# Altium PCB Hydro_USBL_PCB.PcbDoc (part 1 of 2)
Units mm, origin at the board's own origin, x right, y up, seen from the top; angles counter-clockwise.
Board outline 75 x 75 mm, 4 copper layers (Top Layer, Layer 1, Layer 2, Bottom Layer), stack 0.871 mm thick; 273 components, 152 nets, 824 pads, 165 vias.
Unrouted connection lines stored in the file: 155.
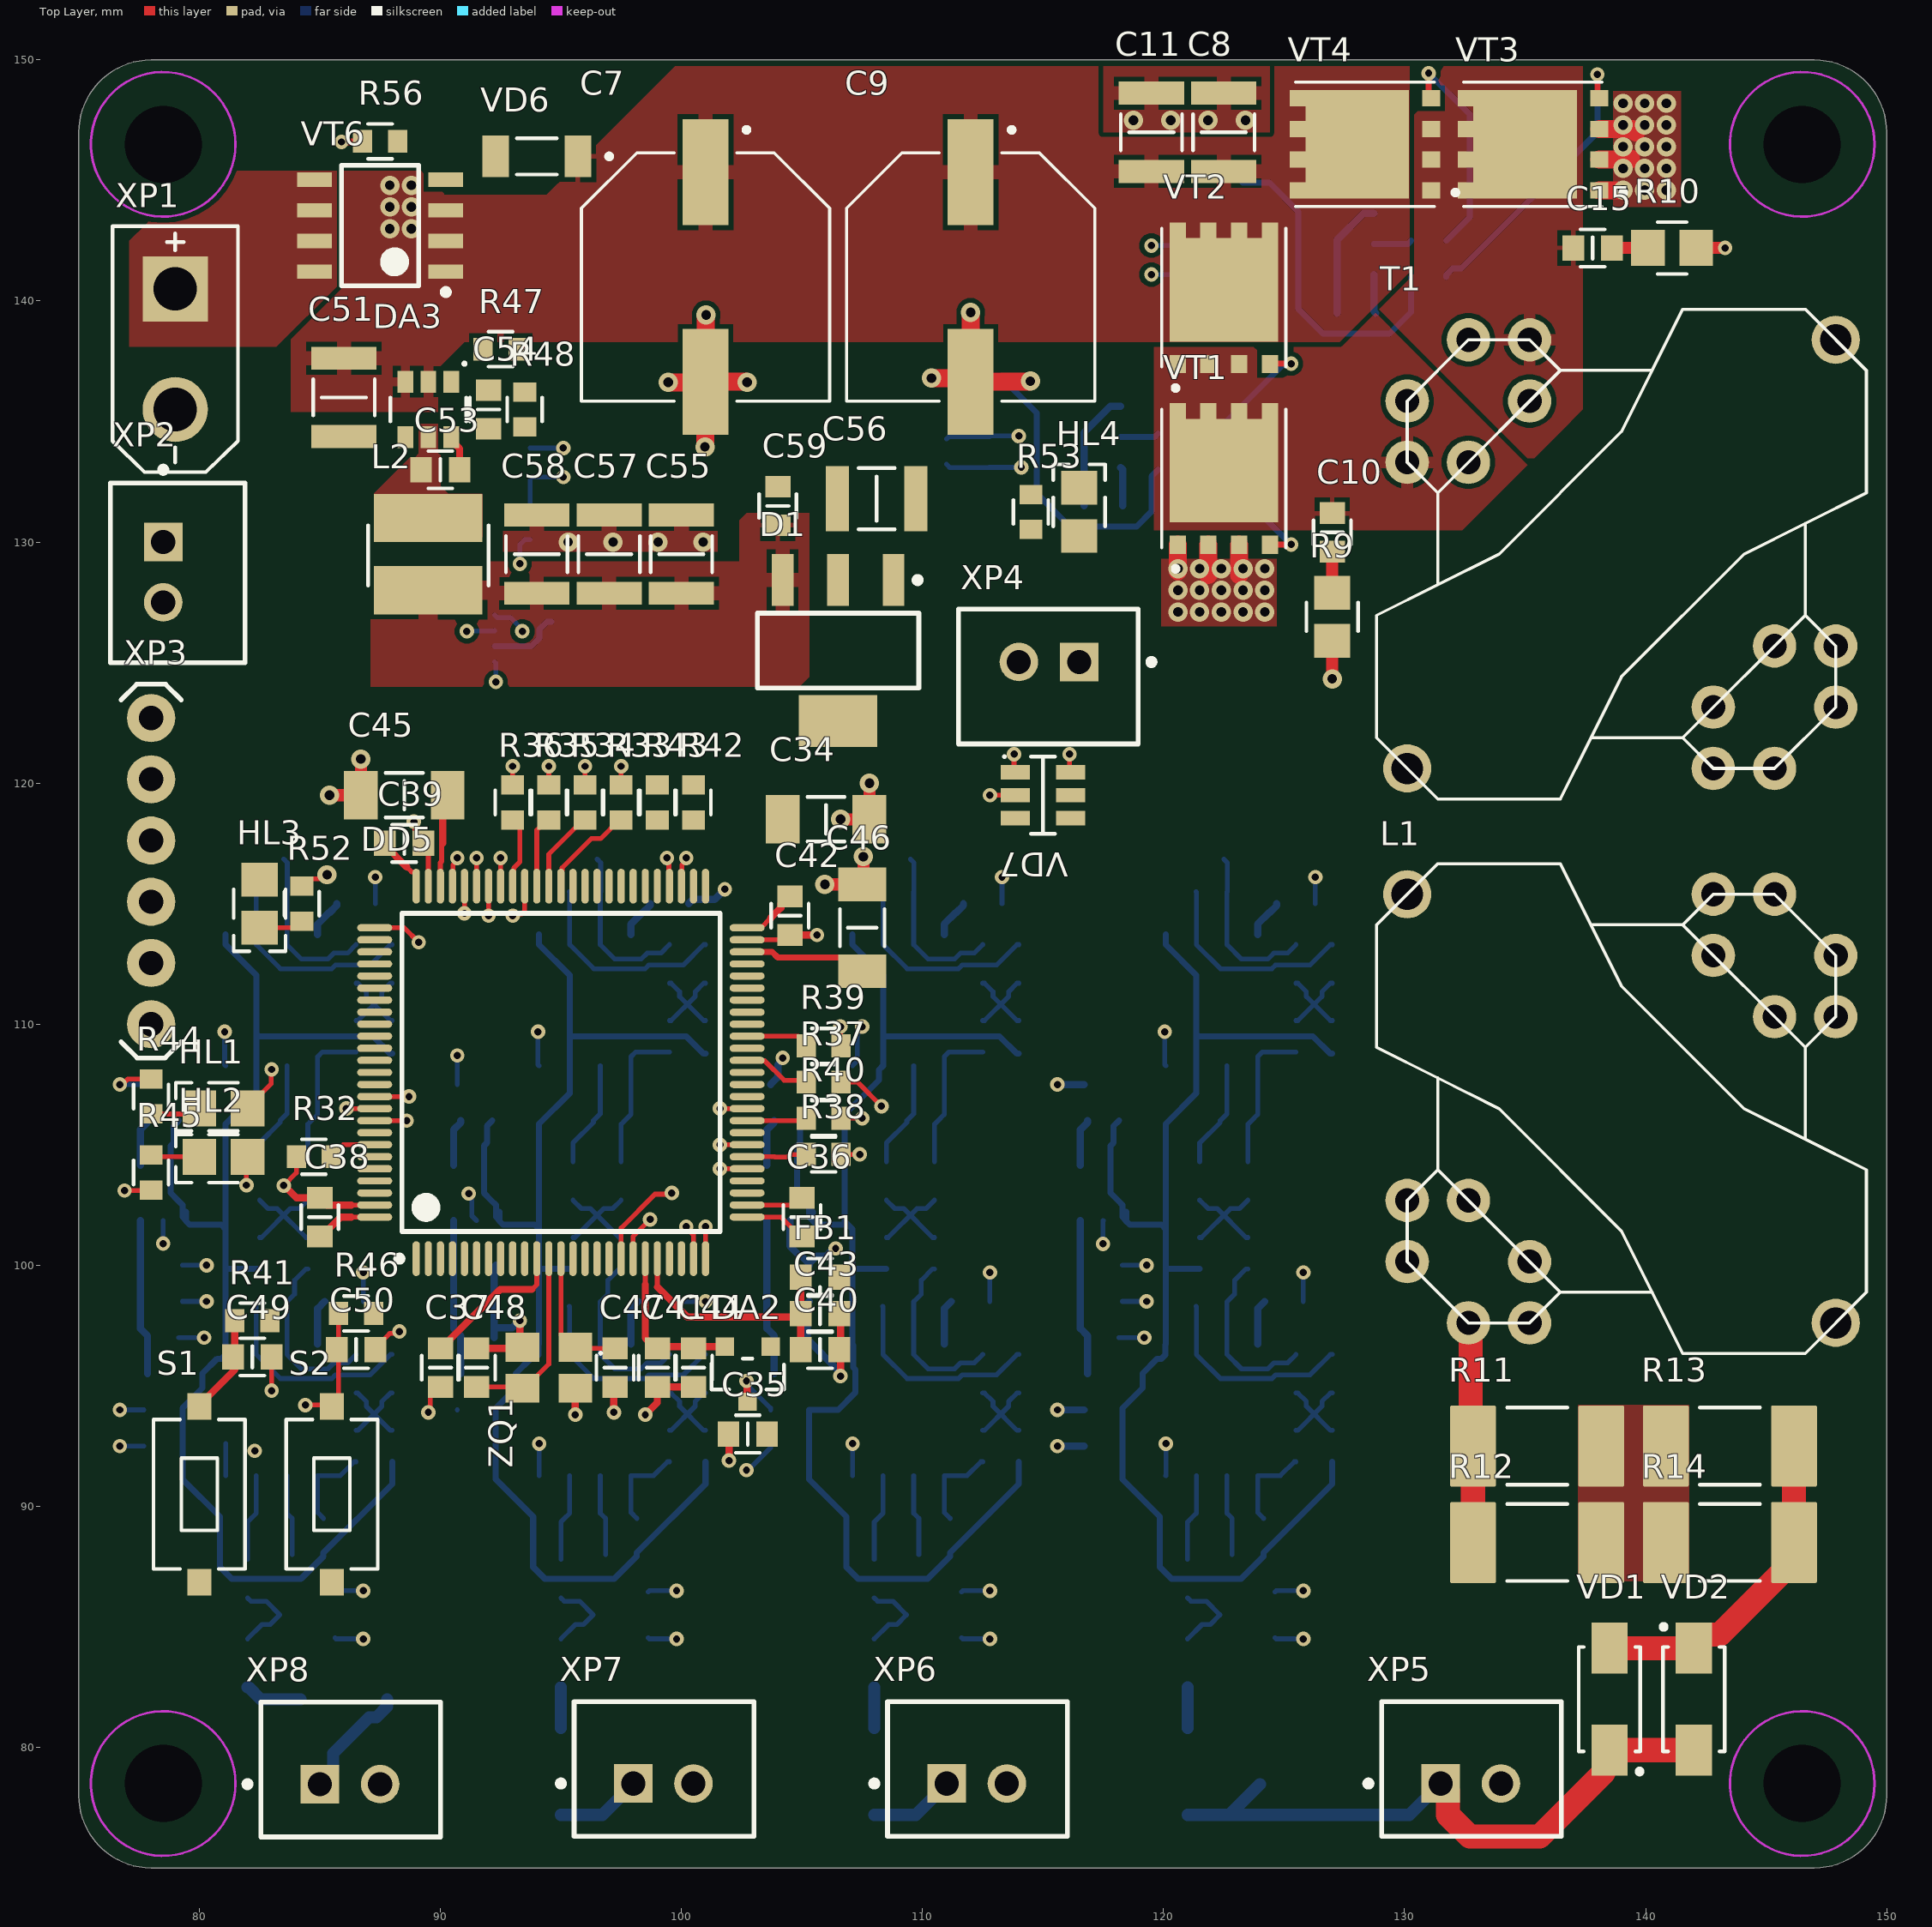
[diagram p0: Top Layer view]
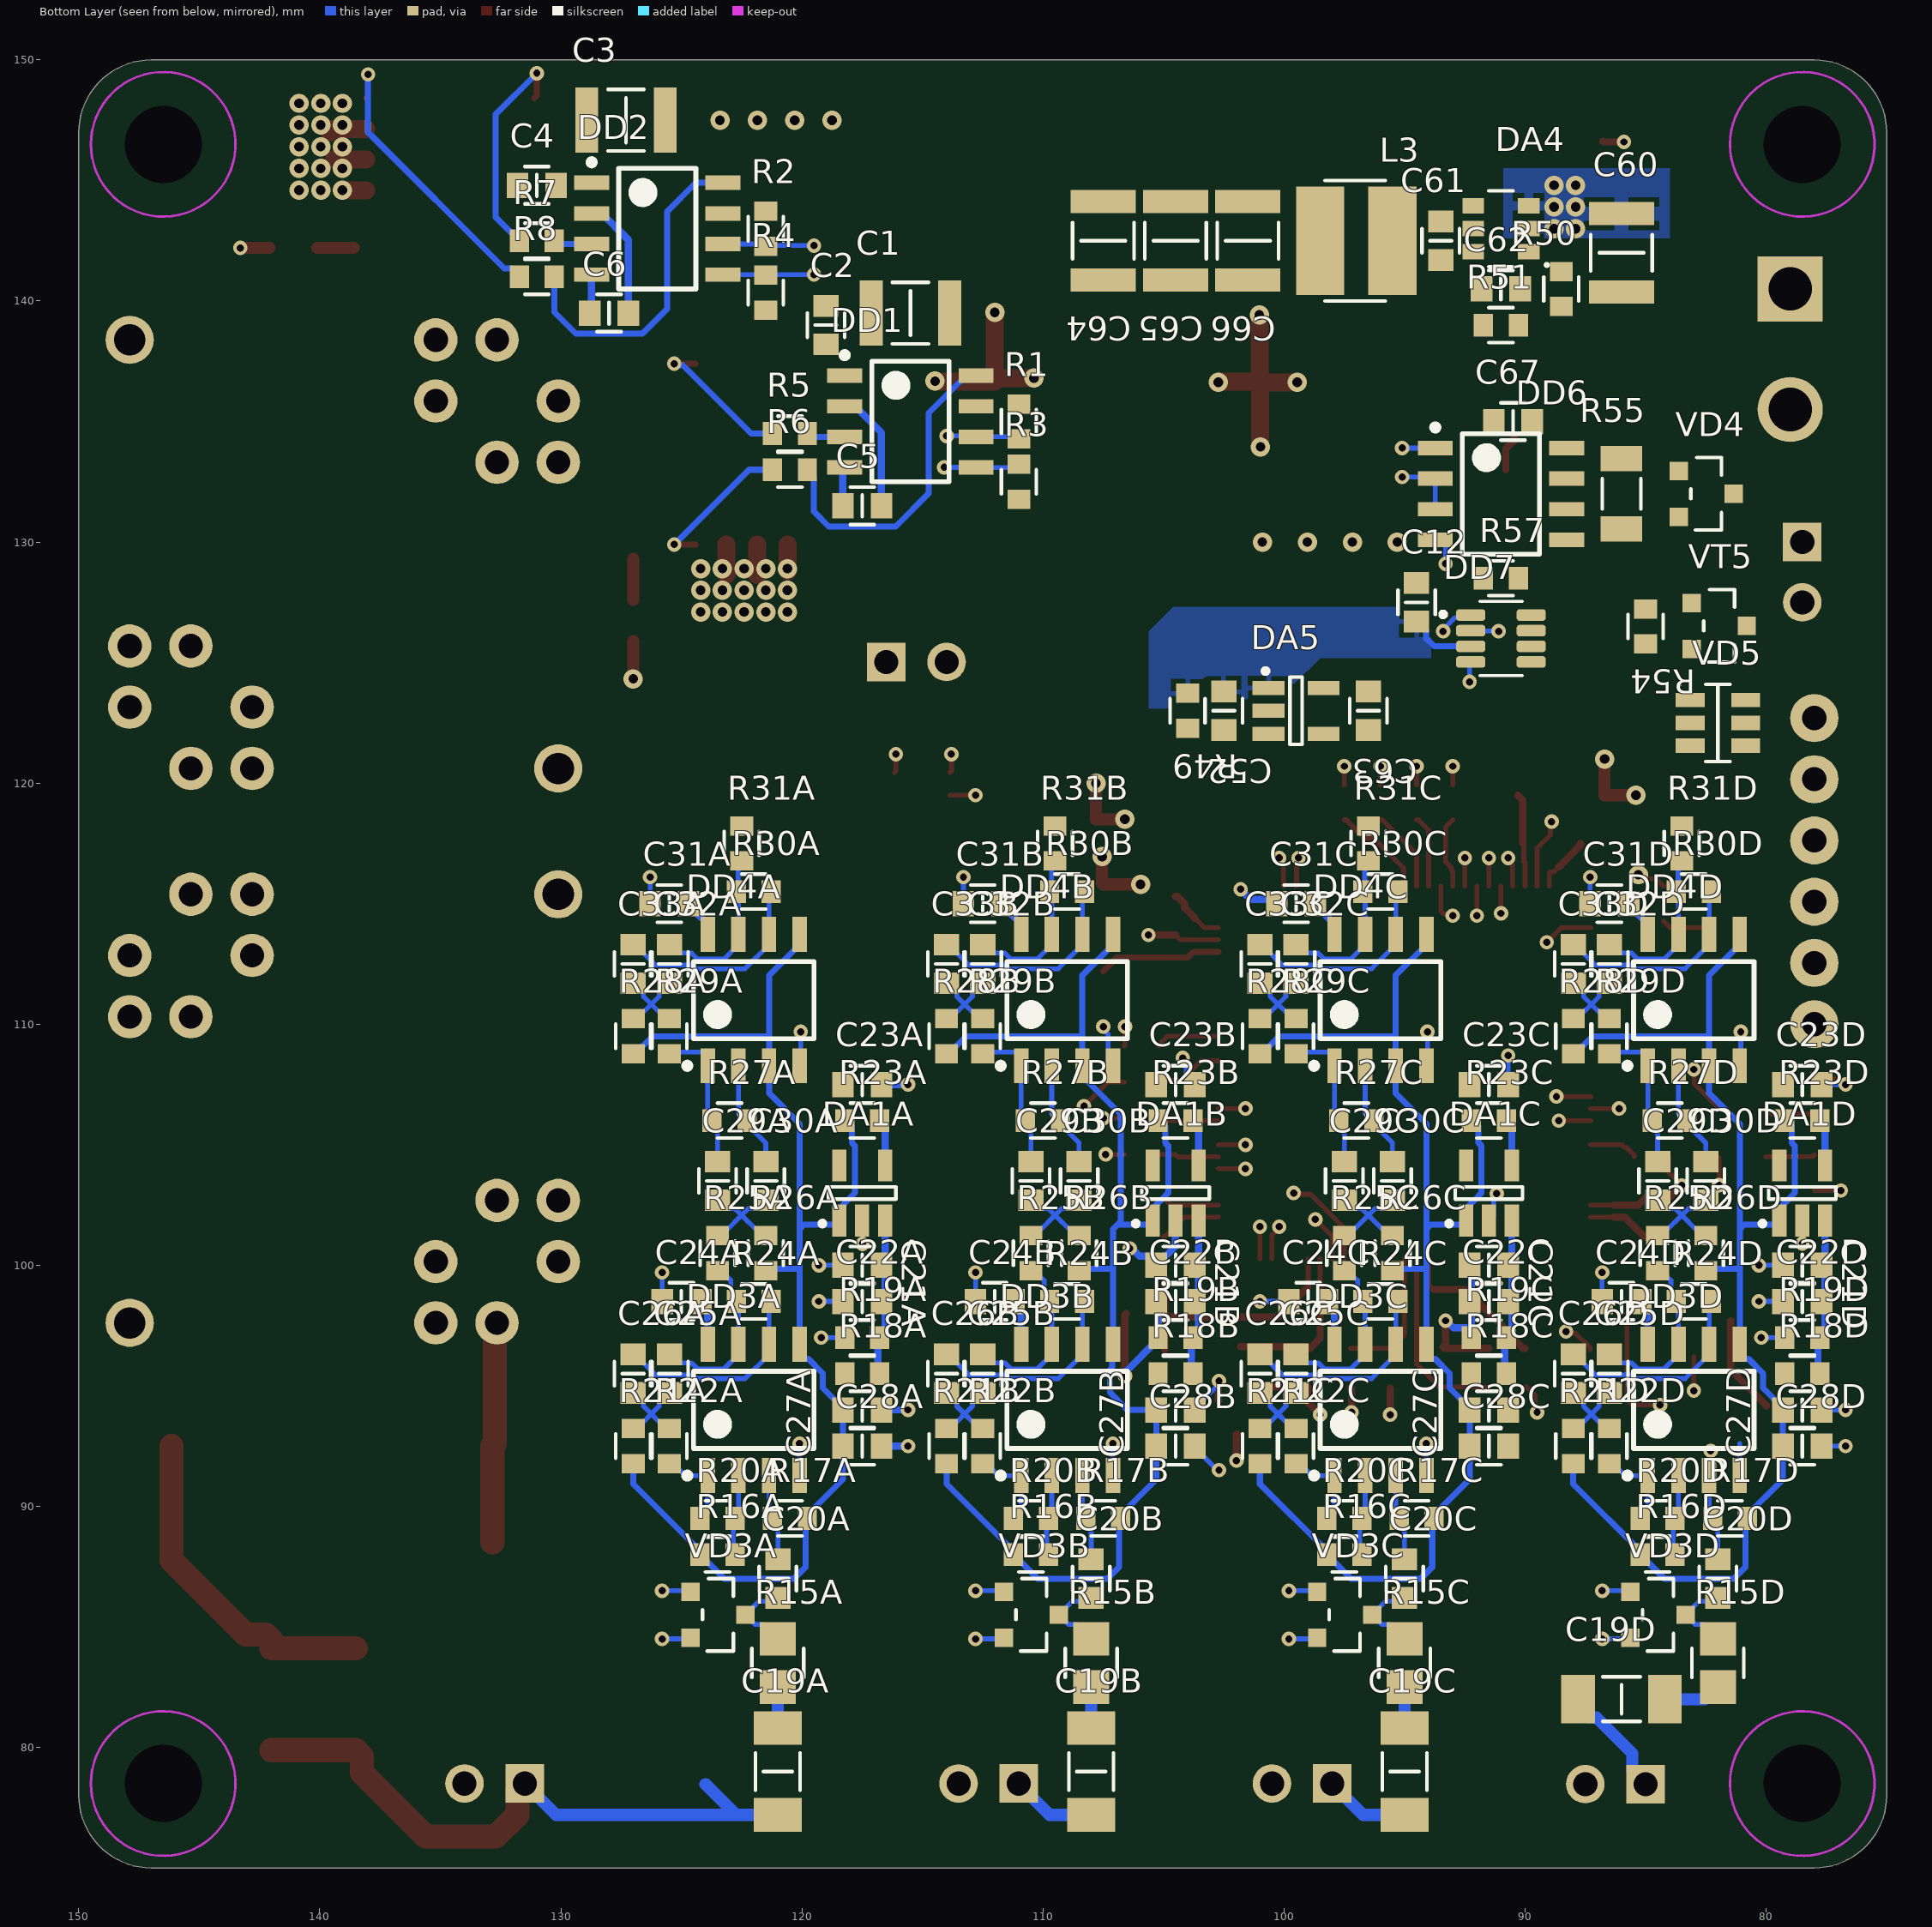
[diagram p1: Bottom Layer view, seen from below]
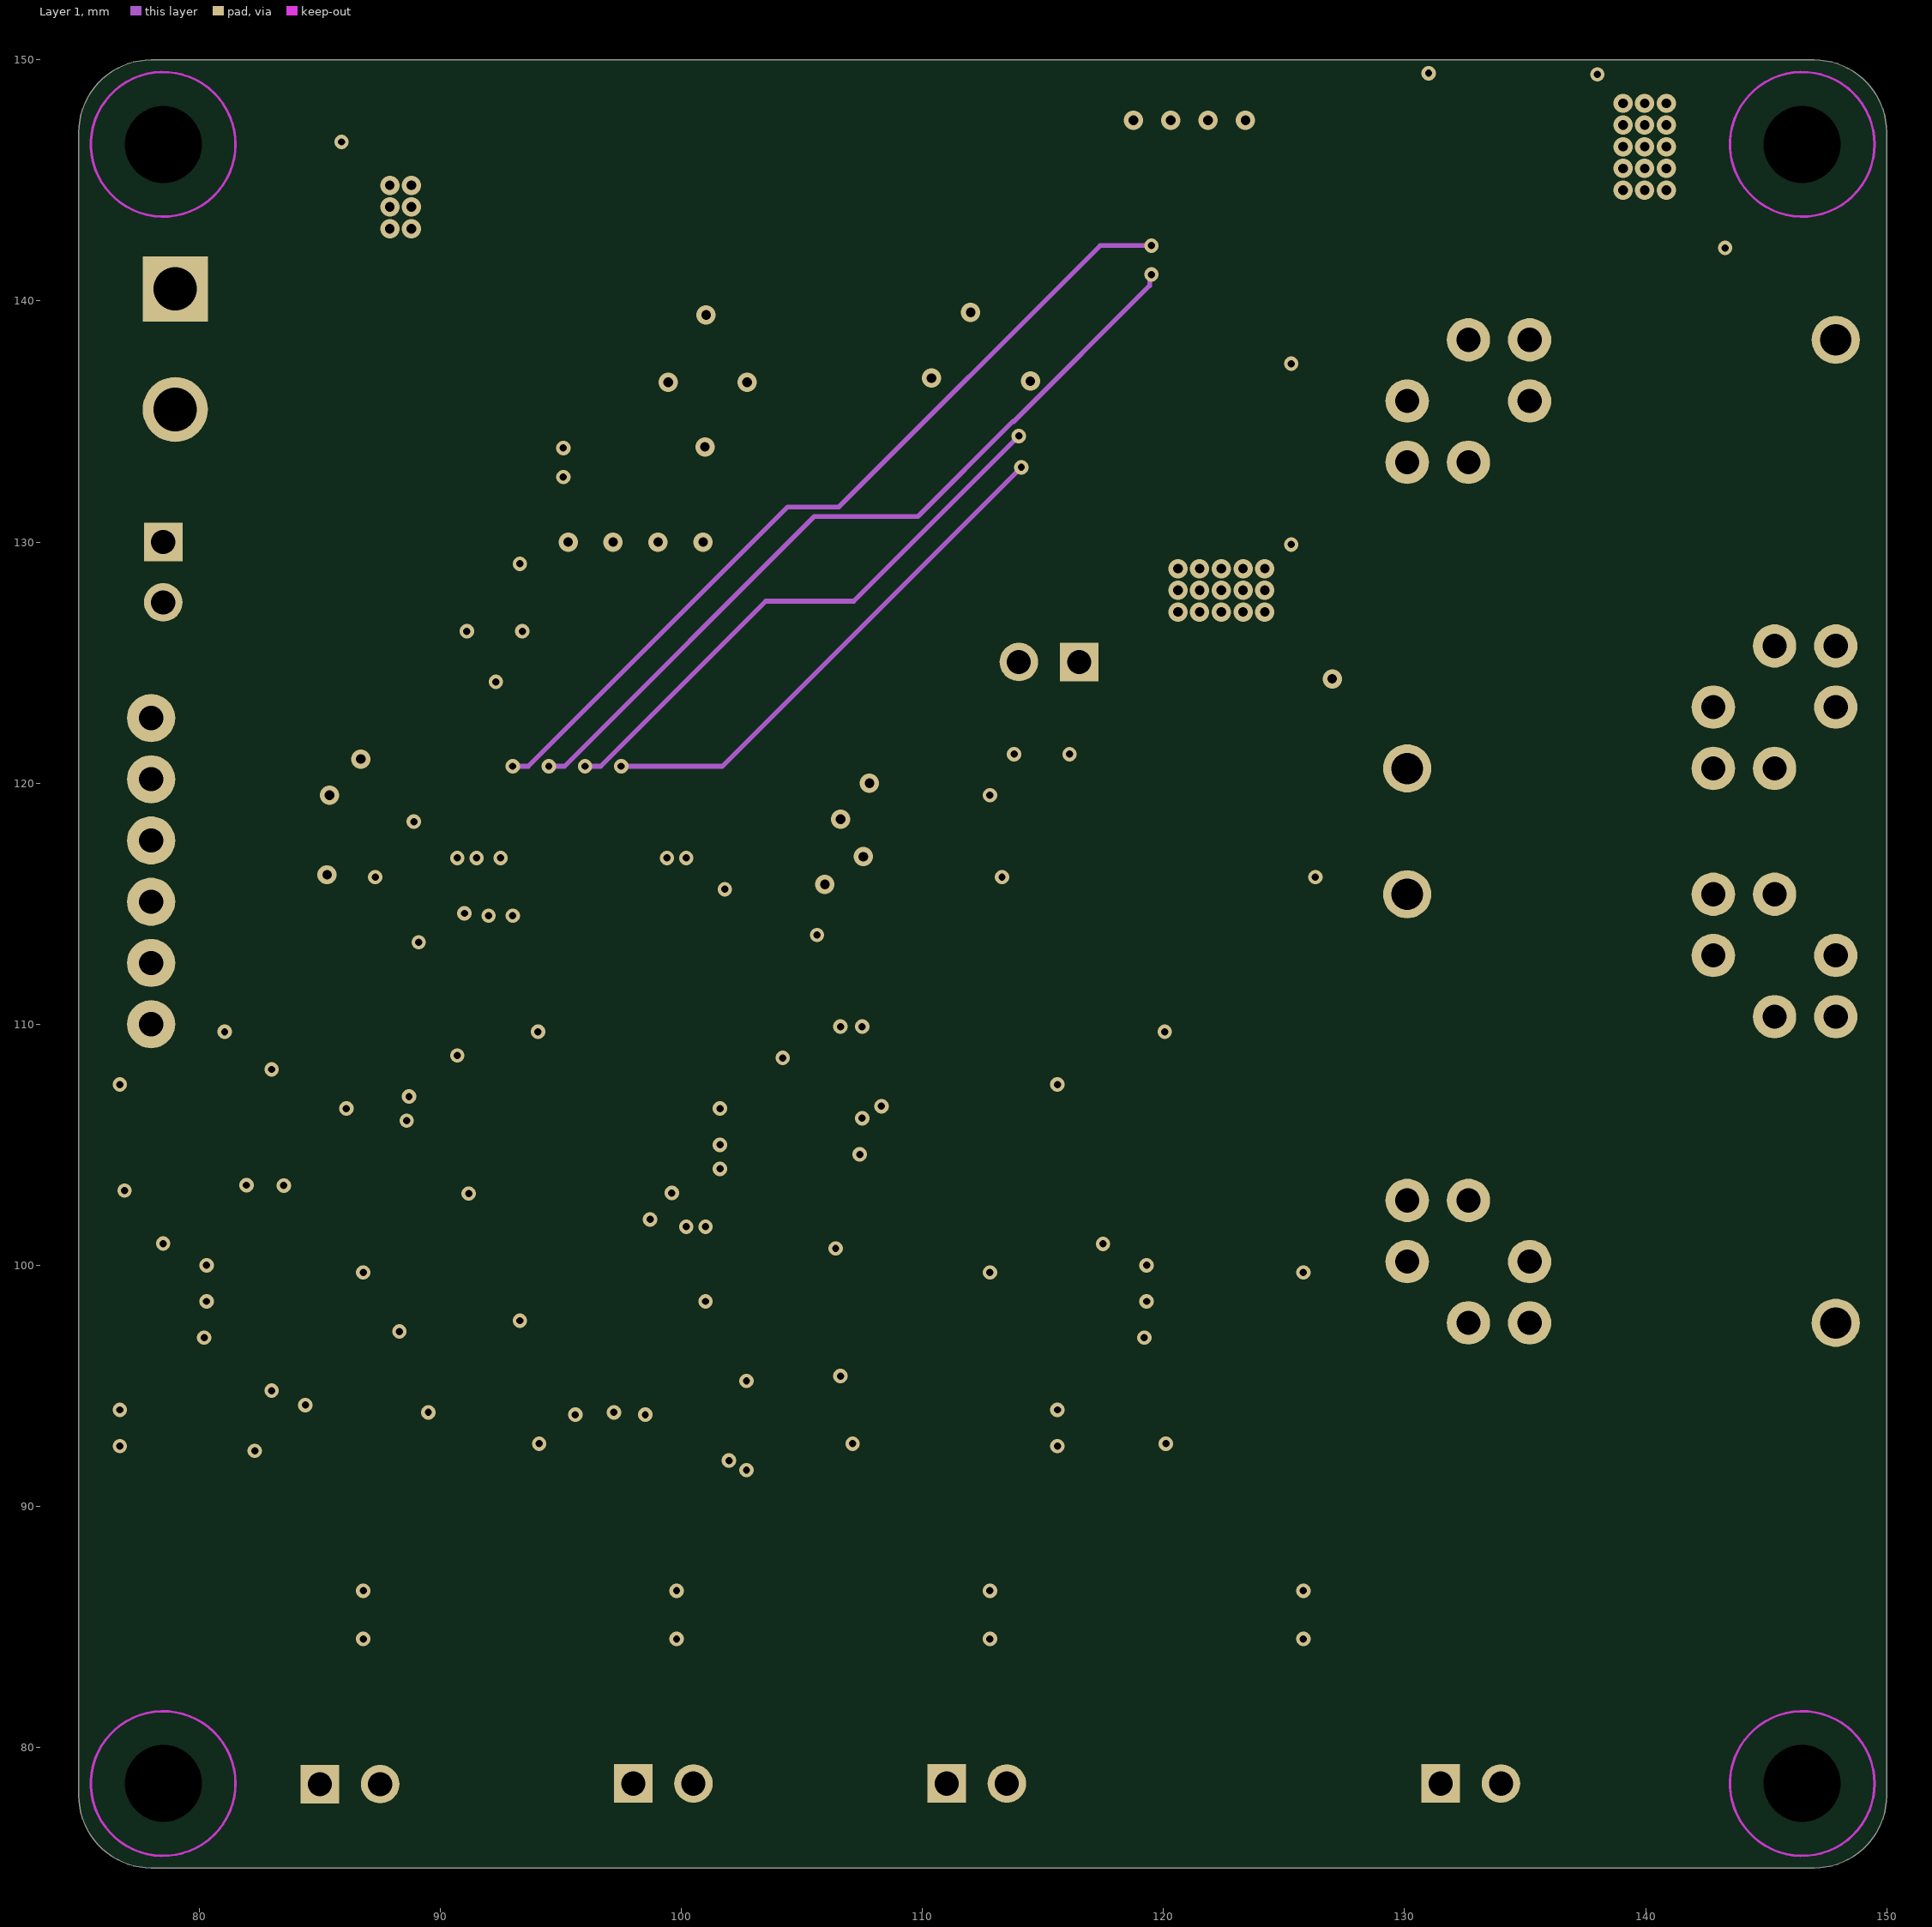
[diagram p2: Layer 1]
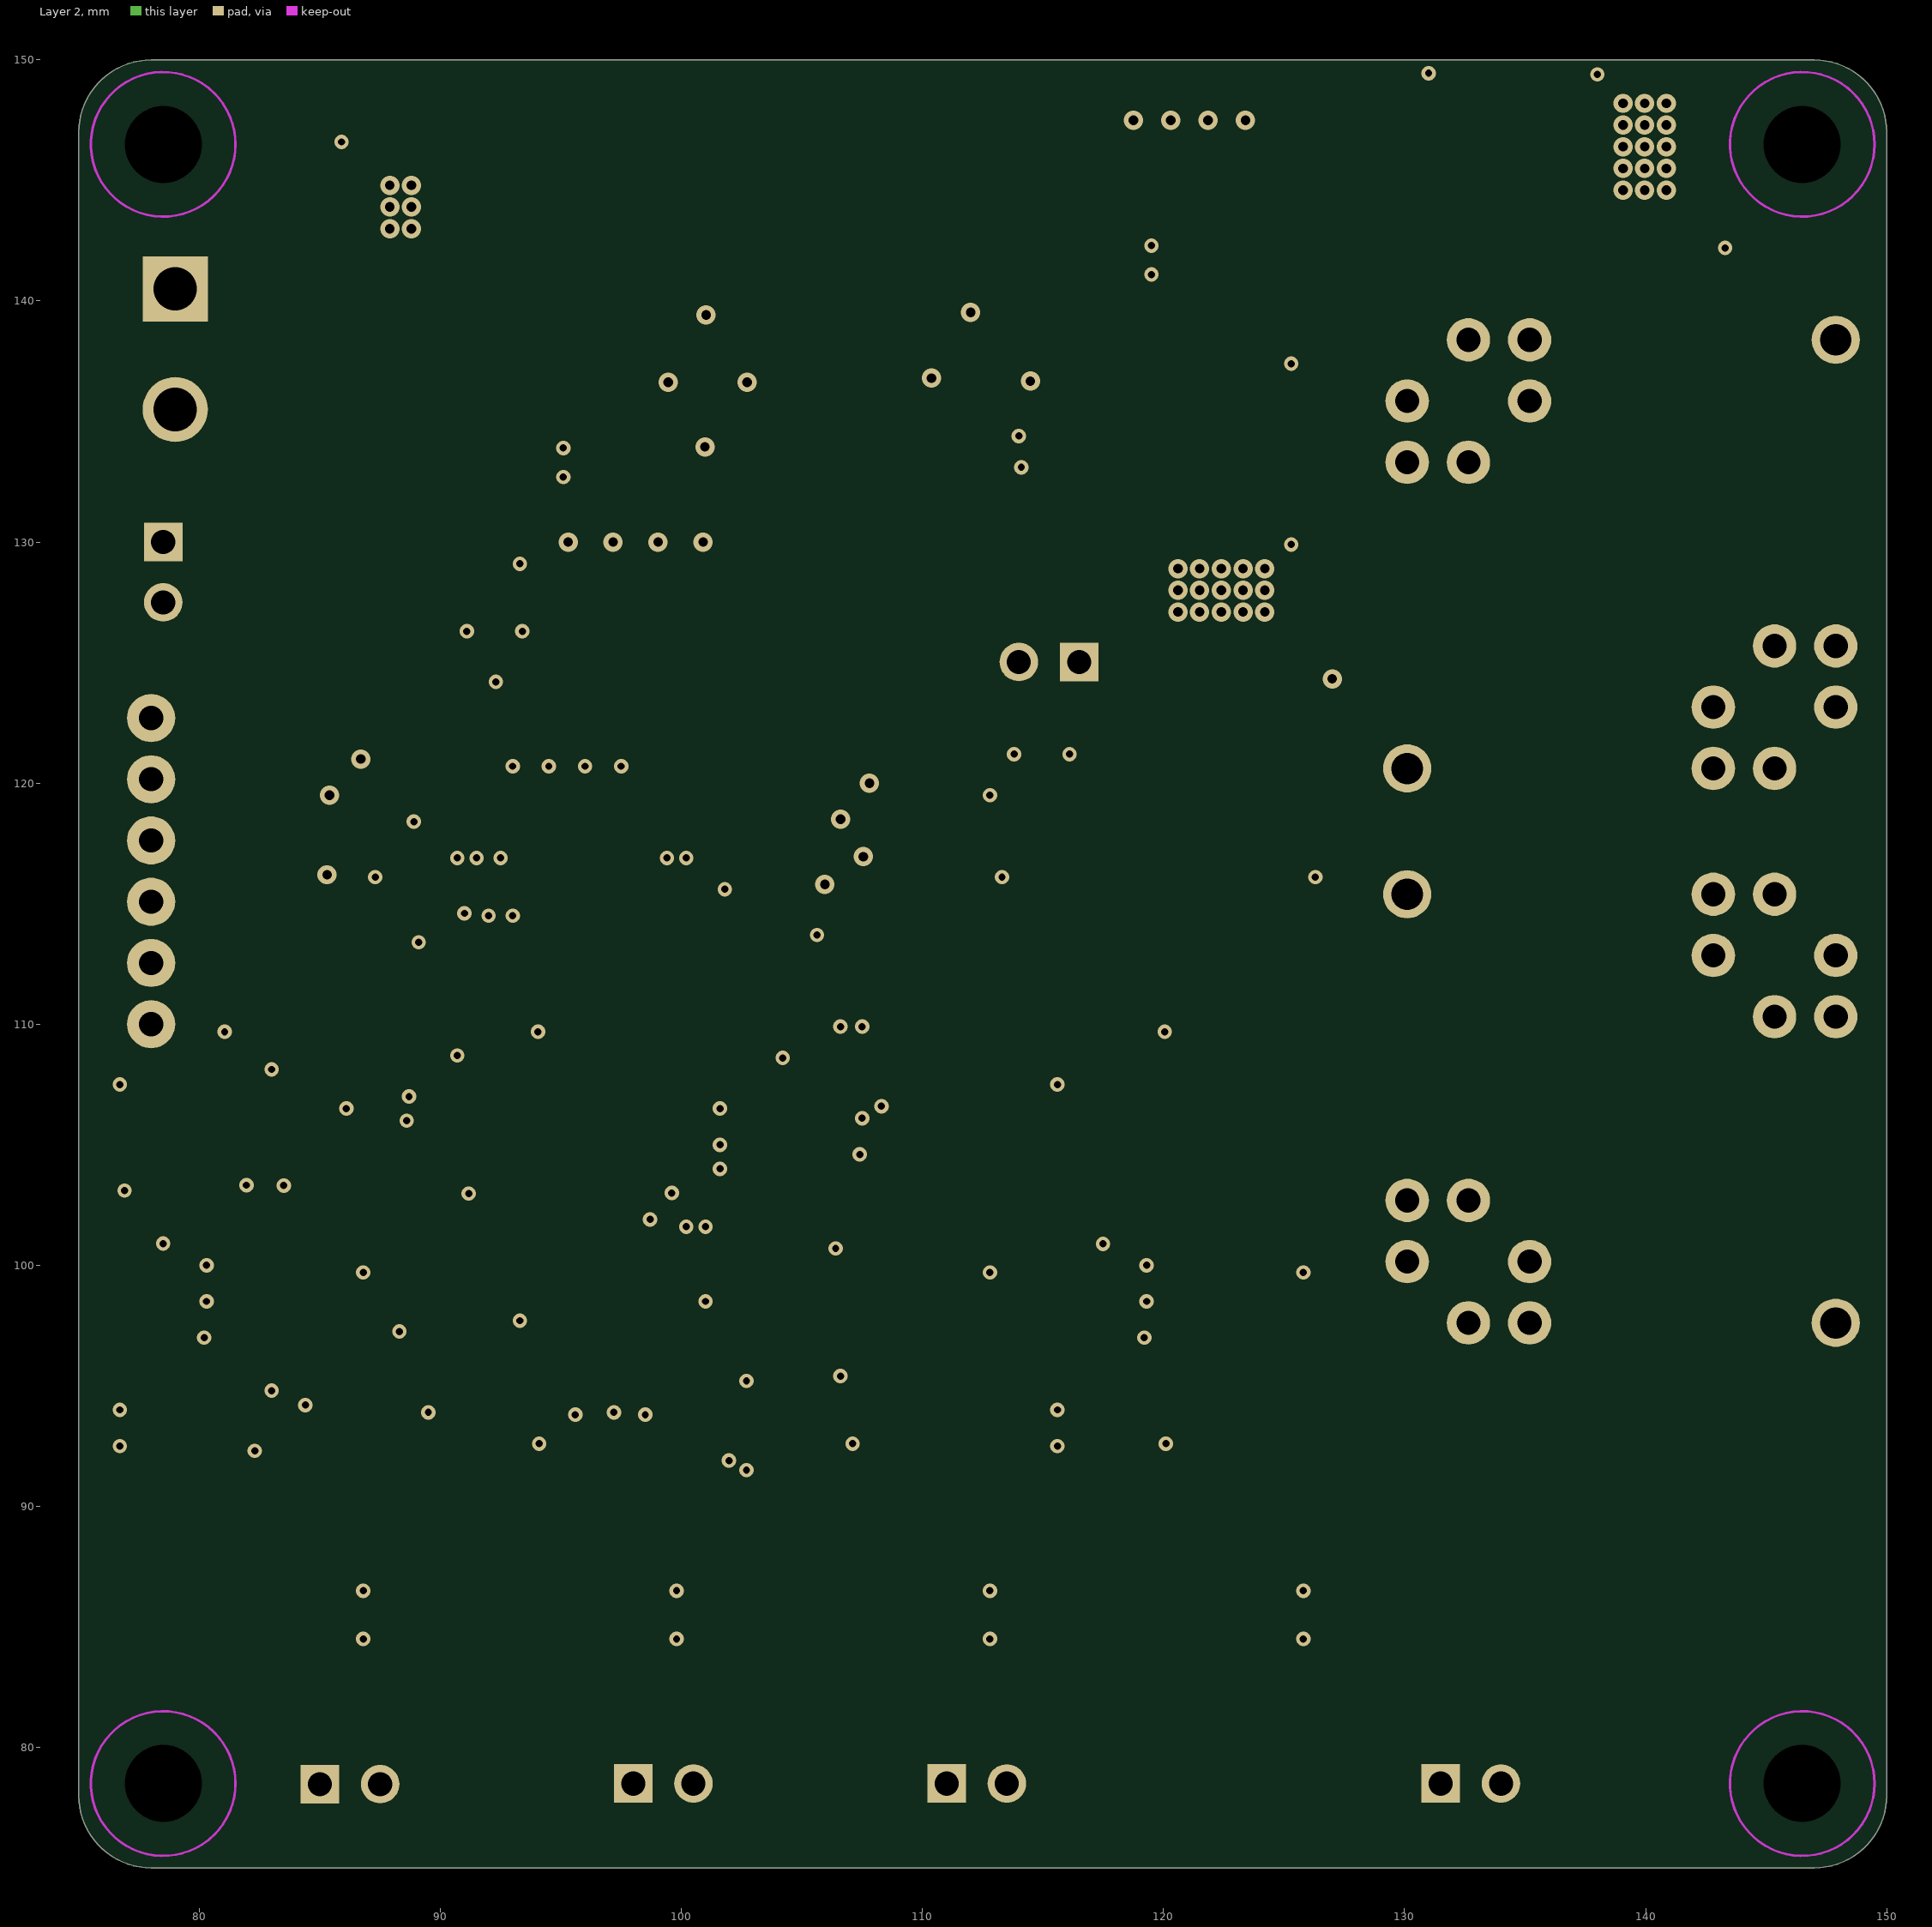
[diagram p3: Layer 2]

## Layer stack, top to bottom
Top Solder: solder mask 0.0102, Solder Resist, Dk 3.5
Top Layer: signal copper 0.0356
Dielectric 2: prepreg 0.115, FR4 PR, Dk 4.2
Layer 1: signal copper 0.035
Dielectric 1: core 0.5, FR4 Tg150, Dk 4.6
Layer 2: signal copper 0.035
Dielectric 3: prepreg 0.115, FR4 PR, Dk 4.2
Bottom Layer: signal copper 0.0356
Bottom Solder: solder mask 0.0102, Solder Resist, Dk 3.5

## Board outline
75,78 75,147 cw(c78,147) 78,150 147,150 cw(c147,147) 150,147 150,78 cw(c147,78) 147,75 78,75 cw(c78,78)

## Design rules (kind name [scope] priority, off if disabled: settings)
AcuteAngle [All] p1: minimum=3.50000000000000E+0001 checktracksonly=FALSE
BoardOutlineClearance "BoardOutlineClearance 1" [All] p1: gap=0.25 ignorepadtopadclearanceinfootprint=FALSE except(0: Arc-SplitContinuation Track-SplitContinuation SMDPad-SplitContinuation THPad-SplitContinuation Via-SplitContinuation Fill-SplitContinuation Poly-SplitContinuation Region-SplitContinuation Text-SplitContinuation) // Milling
BoardOutlineClearance "BoardOutlineClearance 2" [All] p2: gap=0.4 ignorepadtopadclearanceinfootprint=FALSE except(0: Arc-SplitContinuation Track-SplitContinuation SMDPad-SplitContinuation THPad-SplitContinuation Via-SplitContinuation Fill-SplitContinuation Poly-SplitContinuation Region-SplitContinuation Text-SplitContinuation) // V-Cut
Clearance [InNetClass('HV')] p1: gap=0.9 ignorepadtopadclearanceinfootprint=FALSE
Clearance "Schematic Clearance Constraint" [InNet('NetL1_3')] p2: gap=1 ignorepadtopadclearanceinfootprint=FALSE
Clearance "Clearance-1 1 Oz" [All] p3: gap=0.2 ignorepadtopadclearanceinfootprint=FALSE except(0.25: Arc-Hole Track-Hole SMDPad-Hole THPad-Hole Via-Hole Fill-Hole Poly-Hole Region-Hole Text-Hole) // Standart
DiffPairsRouting [InDifferentialPairClass('90OhmDiff')] p1: maxlimit=0.222 minlimit=0.127 mostfreqgap=0.222 toplayer_mingap=0.222 toplayer_minwidth=0.2 toplayer_maxwidth=0.2 toplayer_prefwidth=0.2 midlayer1_maxgap=0.127 midlayer1_prefgap=0.127 midlayer1_minwidth=0.082 midlayer1_maxwidth=0.082 midlayer1_prefwidth=0.082 midlayer2_maxgap=0.127 midlayer2_prefgap=0.127 midlayer2_minwidth=0.082 midlayer2_maxwidth=0.082 midlayer2_prefwidth=0.082 bottomlayer_mingap=0.222 bottomlayer_minwidth=0.2 bottomlayer_maxwidth=0.2 bottomlayer_prefwidth=0.2 impedanceprofiledriven=TRUE impedanceprofileid={9D8E4738-0CD2-4533-A0C9-D04DD6BC2EC3} impedanceprofilevalue=90.000000 maxuncoupledlength=12.7
DiffPairsRouting "DiffPairsRouting 1 Oz" [All] p2: maxlimit=0.25 minlimit=0.2 mostfreqgap=0.2 toplayer_minwidth=0.2 toplayer_maxwidth=0.38 toplayer_prefwidth=0.25 midlayer1_minwidth=0.2 midlayer1_maxwidth=0.38 midlayer1_prefwidth=0.25 midlayer2_minwidth=0.2 midlayer2_maxwidth=0.38 midlayer2_prefwidth=0.25 bottomlayer_minwidth=0.2 bottomlayer_maxwidth=0.38 bottomlayer_prefwidth=0.25 maxuncoupledlength=12.7
HoleSize "Minimum HoleSize" [IsPad] p1: absolutevalues=TRUE maxlimit=5.9 minlimit=0.6 maxpercent=80.000 minpercent=20.000
HoleSize "Minimum HoleSize VIA 1" [IsVia] p2: absolutevalues=TRUE maxlimit=5.9 minlimit=0.3 maxpercent=80.000 minpercent=20.000 // Standart
HoleSize "Minimum HoleSize VIA 2" [IsVia] p3: absolutevalues=TRUE maxlimit=5.9 minlimit=0.2 maxpercent=80.000 minpercent=20.000 // Advance
HoleToHoleClearance Hole2HoleClearance [All] p1: gap=0.25 allowstackedmicrovias=FALSE
MinimumAnnularRing "Minimum AR VIA Standart" [IsVia] p1: minimumring=0.15
MinimumAnnularRing "Minimum AR PAD Standart" [IsPAD] p2: minimumring=0.2
MinimumAnnularRing "Minimum AR VIA Advance" [IsVia] p3: minimumring=0.1
MinimumAnnularRing "Minimum AR PAD Advance" [IsPAD] p4: minimumring=0.15
MinimumSolderMaskSliver "SolderMask Bridge Standart" [All] p1: minsoldermaskwidth=0.15 // All Masks
MinimumSolderMaskSliver "SolderMask Bridge Advance" [All] p2: minsoldermaskwidth=0.1 // Mask LDI
PlaneClearance "PlaneClearance 3 Oz" [All] p1 off: clearance=0.35
PlaneClearance "PlaneClearance 2 Oz" [All] p2 off: clearance=0.3
PlaneClearance "PlaneClearance 1 Oz" [All] p3: clearance=0.2
PlaneClearance "PlaneClearance-1 1/2 Oz" [All] p4 off: clearance=0.2 // Standart
PlaneClearance "PlaneClearance-2 1/2 Oz" [All] p5 off: clearance=0.15 // Advance
PlaneConnect "TermalConnect 3 Oz" [All] p1 off: planeconnectstyle=Relief reliefexpansion=0.2 reliefentries=4 reliefconductorwidth=0.35 reliefairgap=0.35 // Standart
PlaneConnect "TermalConnect 2 Oz" [All] p2 off: planeconnectstyle=Relief reliefexpansion=0.2 reliefentries=4 reliefconductorwidth=0.3 reliefairgap=0.3 // Standart
PlaneConnect "TermalConnect-1 1 Oz" [All] p3: planeconnectstyle=Relief reliefexpansion=0.2 reliefentries=4 reliefconductorwidth=0.2 reliefairgap=0.2 // Standart
PlaneConnect "TermalConnect-2 1 Oz" [All] p4 off: pad.planeconnectstyle=Relief pad.reliefexpansion=0.15 pad.reliefentries=4 pad.reliefconductorwidth=0.2 pad.reliefairgap=0.2 via.planeconnectstyle=Direct via.reliefexpansion=0.15 via.reliefentries=4 via.reliefconductorwidth=0.15 via.reliefairgap=0.15 // Advance
PlaneConnect "TermalConnect-1 1/2 Oz" [All] p5 off: planeconnectstyle=Relief reliefexpansion=0.2 reliefentries=4 reliefconductorwidth=0.2 reliefairgap=0.2 // Standart
PlaneConnect "TermalConnect-2 1/2 Oz" [All] p6 off: pad.planeconnectstyle=Relief pad.reliefexpansion=0.15 pad.reliefentries=4 pad.reliefconductorwidth=0.15 pad.reliefairgap=0.15 via.planeconnectstyle=Direct via.reliefexpansion=0.15 via.reliefentries=4 via.reliefconductorwidth=0.15 via.reliefairgap=0.15 // Advance
PolygonConnect PolygonConnect_5 [InNet('NetC53_2')] p1: connectstyle=Direct reliefconductorwidth=0.254 reliefentries=4 polygonreliefangle="90 Angle" airgapwidth=0.254
PolygonConnect PolygonConnect_6 [HasFootprint('SP43')] p2: thpad.connectstyle=Relief thpad.reliefconductorwidth=0.8 thpad.reliefentries=4 thpad.polygonreliefangle="90 Angle" thpad.airgapwidth=0.2 smdpad.connectstyle=Relief smdpad.reliefconductorwidth=0.8 smdpad.reliefentries=4 smdpad.polygonreliefangle="90 Angle" smdpad.airgapwidth=0.2 via.connectstyle=Direct via.reliefconductorwidth=0.254 via.reliefentries=4 via.polygonreliefangle="90 Angle" via.airgapwidth=0.254
PolygonConnect PolygonConnect_4 [HasFootprint('RM8_trans')] p3: connectstyle=Relief reliefconductorwidth=0.5 reliefentries=4 polygonreliefangle="90 Angle" airgapwidth=0.2
PolygonConnect PolygonConnect_3 [HasFootprint('TSOT26')] p4: connectstyle=Relief reliefconductorwidth=0.4 reliefentries=4 polygonreliefangle="90 Angle" airgapwidth=0.2
PolygonConnect PolygonConnect_2 [(HasFootprint('1210C') OR HasFootprint('1206C')) Or (HasFootprint('CAP_SMD_10x12,7')) or (HasFootprint('SOT223'))] p5: connectstyle=Relief reliefconductorwidth=0.6 reliefentries=4 polygonreliefangle="90 Angle" airgapwidth=0.2
PolygonConnect PolygonConnect_1 [InNetClass('Power')] p6: connectstyle=Direct reliefconductorwidth=0.254 reliefentries=4 polygonreliefangle="90 Angle" airgapwidth=0.254
PolygonConnect [(HasFootprint('XT30UPB-M') OR HasFootprint('SON-8_5x6')) OR (HasFootprint('RM8')) Or HasFootprint('2512R') OR InComponent('VT6')] p7: connectstyle=Direct reliefconductorwidth=0.254 reliefentries=4 polygonreliefangle="90 Angle" airgapwidth=0.254
PolygonConnect "PolygonConnect-1 1 Oz" [All] p8: thpad.connectstyle=Relief thpad.reliefconductorwidth=0.2 thpad.reliefentries=4 thpad.polygonreliefangle="90 Angle" thpad.airgapwidth=0.2 smdpad.connectstyle=Relief smdpad.reliefconductorwidth=0.2 smdpad.reliefentries=4 smdpad.polygonreliefangle="90 Angle" smdpad.airgapwidth=0.2 via.connectstyle=Direct via.reliefconductorwidth=0.254 via.reliefentries=4 via.polygonreliefangle="90 Angle" via.airgapwidth=0.254 // Standart
RoomDefinition C [InComponentClass('C')] p1: confinementstyle=ConfineIn formatcopy=TRUE lockcomponents=FALSE outline 103,118.5 103,76.2 115,76.2 115,118.5
RoomDefinition E [InComponentClass('E')] p2: confinementstyle=ConfineIn formatcopy=TRUE lockcomponents=FALSE outline 77,118.5 77,76.2 89,76.2 89,118.5
RoomDefinition B [InComponentClass('B')] p3: confinementstyle=ConfineIn formatcopy=TRUE lockcomponents=FALSE outline 116,118.5 116,76.2 128,76.2 128,118.5
RoomDefinition D [InComponentClass('D')] p4: confinementstyle=ConfineIn formatcopy=TRUE lockcomponents=FALSE outline 90,118.5 90,76.2 102,76.2 102,118.5
RoomDefinition STM32 [InComponentClass('STM32')] p5 off: confinementstyle=ConfineIn formatcopy=TRUE lockcomponents=FALSE outline 96.5,229.5 371.5,229.5 371.5,251.5 96.5,251.5
RoomDefinition Power [InComponentClass('Power')] p6 off: confinementstyle=ConfineIn formatcopy=TRUE lockcomponents=FALSE outline 175.875,176 377.875,176 377.875,187 175.875,187
RoomDefinition "High voltage amp" [InComponentClass('High voltage amp')] p7 off: confinementstyle=ConfineIn formatcopy=TRUE lockcomponents=FALSE outline 181,90.5 455.5,90.5 455.5,142 181,142
RoomDefinition Connectors [InComponentClass('Connectors')] p8 off: confinementstyle=ConfineIn formatcopy=TRUE lockcomponents=FALSE outline 255.775,148.595 398.775,148.595 398.775,168.595 255.775,168.595
RoutingCorners [All] p1 off: cornerstyle=45-Degree minsetback=2.54 maxsetback=2.54
RoutingVias [All] p1: holewidth=0.4 width=0.8 viastyle="Through Hole" minholewidth=0.3 minwidth=0.6 maxholewidth=5.9 maxwidth=6.4
SilkToSilkClearance Silk2SilkClearance [All] p1 off: silktosilkclearance=0.15
SilkToSolderMaskClearance Silk2SolderMaskClearance [IsPad] p1 off: minsilkscreentomaskgap=0.15 clearancetoexposedcopper=TRUE
SolderMaskExpansion [IsVia] p1: expansion=0.102 istentingtop=TRUE
SolderMaskExpansion SolderMaskExpansion-1 [All] p2: expansion=0.05 istentingtop=FALSE // Standart
SolderMaskExpansion "SolderMaskExpansion LDI" [All] p3: expansion=0.025 istentingtop=FALSE // Advance
SupplyNets "Schematic Supply Nets_7" [InNet('+24В')] p1: voltage=0.000
SupplyNets "Schematic Supply Nets_6" [InNet('VREF_MCU')] p2: voltage=0.000
SupplyNets "Schematic Supply Nets_5" [InNet('+10В')] p3: voltage=0.000
SupplyNets "Schematic Supply Nets_4" [InNet('+5В')] p4: voltage=0.000
SupplyNets "Schematic Supply Nets_3" [InNet('GND')] p5: voltage=0.000
SupplyNets "Schematic Supply Nets_2" [InNet('VDDA')] p6: voltage=0.000
SupplyNets "Schematic Supply Nets" [InNet('VDD')] p7: voltage=0.000
UnRoutedNet [All] p1: checkbadconnections=TRUE
Width "Width 1 Oz" [All] p1: maxlimit=10 minlimit=0.2 preferedwidth=0.2 checkconnectedcopper=TRUE
20 further rules are at their usual default settings.

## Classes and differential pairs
differential pair class 90OhmDiff: USB
net class HV: ANT1 ANT2 ANT3 ANT4 NetL1_3 NetL1_9 NetR11_2 NetR13_2
component class STM32: C34 C35 C36 C37 C38 C39 C40 C41 C42 C43 C44 C45 C46 C47 C48 C49 C50 DA2 DD5 FB1 HL1 HL2 R32 R33 R34 R35 R36 R37 R38 R39 R40 R41 R42 R43 R44 R45 R46 S1 S2 ZQ1
component class Power: C51 C52 C53 C54 C55 C56 C57 C58 C59 C60 C61 C62 C63 C64 C65 C66 D1 DA3 DA4 DA5 HL3 HL4 L2 L3 R47 R48 R49 R50 R51 R52 R53
component class "High voltage amp": C1 C2 C3 C4 C5 C6 C7 C8 C9 C10 C11 C15 DD1 DD2 L1 R1 R2 R3 R4 R5 R6 R7 R8 R9 R10 R11 R12 R13 R14 T1 VD1 VD2 VT1 VT2 VT3 VT4
component class Connectors: C12 C67 DD6 DD7 R54 R55 R56 R57 VD4 VD5 VD6 VD7 VT5 VT6 XP1 XP2 XP3 XP4 XP5 XP6 XP7 XP8
net class ANT[1..4]: ANT1 ANT2 ANT3 ANT4
net class ADC[1..4]: ADC1 ADC2 ADC3 ADC4
channel class Analog_Filter: B C D E
component class E: C19D C20D C21D C22D C23D C24D C25D C26D C27D C28D C29D C30D C31D C32D C33D DA1D DD3D DD4D R15D R16D R17D R18D R19D R20D R21D R22D R23D R24D R25D R26D R27D R28D R29D R30D R31D VD3D
component class D: C19C C20C C21C C22C C23C C24C C25C C26C C27C C28C C29C C30C C31C C32C C33C DA1C DD3C DD4C R15C R16C R17C R18C R19C R20C R21C R22C R23C R24C R25C R26C R27C R28C R29C R30C R31C VD3C
component class C: C19B C20B C21B C22B C23B C24B C25B C26B C27B C28B C29B C30B C31B C32B C33B DA1B DD3B DD4B R15B R16B R17B R18B R19B R20B R21B R22B R23B R24B R25B R26B R27B R28B R29B R30B R31B VD3B
component class B: C19A C20A C21A C22A C23A C24A C25A C26A C27A C28A C29A C30A C31A C32A C33A DA1A DD3A DD4A R15A R16A R17A R18A R19A R20A R21A R22A R23A R24A R25A R26A R27A R28A R29A R30A R31A VD3A
differential pair RS485_6: +RS485_6_P -RS485_6_N
differential pair USB: +USB_P -USB_N

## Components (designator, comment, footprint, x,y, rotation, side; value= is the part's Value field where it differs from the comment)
C1 "Capacitor" 1210C 115.5,139.5 r180 bottom value="10 мк"
C2 "Capacitor" 0603C 119,139 r270 bottom value="0,1 мк"
C3 "Capacitor" 1210C 127.3,147.5 r0 bottom value="10 мк"
C4 "Capacitor" 0603C 131,144.8 r180 bottom value="0,1 мк"
C5 "Capacitor" 0603C 117.5,131.5 r0 bottom value="1 мк"
C6 "Capacitor" 0603C 128,139.5 r0 bottom value="1 мк"
C7 "Capacitor" CAP_SMD_10x12,7 101,141 r270 top value="68 мк"
C8 "Capacitor" 1210C 122.5,147 r270 top value="10 мк"
C9 "Capacitor" CAP_SMD_10x12,7 112,141 r270 top value="68 мк"
C10 "Capacitor" 0603C 127,130.4 r90 top value="1 н"
C11 "Capacitor" 1210C 119.5,147 r270 top value="10 мк"
C12 "Capacitor" 0603C 94.5,127.5 r270 bottom value="0,1 мк"
C15 "Capacitor" 0603C 137.8,142.2 r180 top value="1 н"
C19A "Capacitor" 1206C 121,79 r90 bottom value="100 п" (schematic designator C19)
C19B "Capacitor" 1206C 108,79 r90 bottom value="100 п" (schematic designator C19)
C19C "Capacitor" 1206C 95,79 r90 bottom value="100 п" (schematic designator C19)
C19D "Capacitor" 1206C 86,82 r180 bottom value="100 п" (schematic designator C19)
C20A "Capacitor" 0603C 121,87 r90 bottom value="1 н" (schematic designator C20)
C20B "Capacitor" 0603C 108,87 r90 bottom value="1 н" (schematic designator C20)
C20C "Capacitor" 0603C 95,87 r90 bottom value="1 н" (schematic designator C20)
C20D "Capacitor" 0603C 82,87 r90 bottom value="1 н" (schematic designator C20)
C21A "Capacitor" 0603C 117.5,100 r180 bottom value="10 мк" (schematic designator C21)
C21B "Capacitor" 0603C 104.5,100 r180 bottom value="10 мк" (schematic designator C21)
C21C "Capacitor" 0603C 91.5,100 r180 bottom value="10 мк" (schematic designator C21)
C21D "Capacitor" 0603C 78.5,100 r180 bottom value="10 мк" (schematic designator C21)
C22A "Capacitor" 0603C 117.5,98.5 r180 bottom value="0,1 мк" (schematic designator C22)
C22B "Capacitor" 0603C 104.5,98.5 r180 bottom value="0,1 мк" (schematic designator C22)
C22C "Capacitor" 0603C 91.5,98.5 r180 bottom value="0,1 мк" (schematic designator C22)
C22D "Capacitor" 0603C 78.5,98.5 r180 bottom value="0,1 мк" (schematic designator C22)
C23A "Capacitor" 0603C 117.5,107.5 r0 bottom value="0,1 мк" (schematic designator C23)
C23B "Capacitor" 0603C 104.5,107.5 r0 bottom value="0,1 мк" (schematic designator C23)
C23C "Capacitor" 0603C 91.5,107.5 r0 bottom value="0,1 мк" (schematic designator C23)
C23D "Capacitor" 0603C 78.5,107.5 r0 bottom value="0,1 мк" (schematic designator C23)
C24A "Capacitor" 0603C 125,98.5 r180 bottom value="0,1 мк" (schematic designator C24)
C24B "Capacitor" 0603C 112,98.5 r180 bottom value="0,1 мк" (schematic designator C24)
C24C "Capacitor" 0603C 99,98.5 r180 bottom value="0,1 мк" (schematic designator C24)
C24D "Capacitor" 0603C 86,98.5 r180 bottom value="0,1 мк" (schematic designator C24)
C25A "Capacitor" 0603C 125.5,95.5 r90 bottom value="3,3 н" (schematic designator C25)
C25B "Capacitor" 0603C 112.5,95.5 r90 bottom value="3,3 н" (schematic designator C25)
C25C "Capacitor" 0603C 99.5,95.5 r90 bottom value="3,3 н" (schematic designator C25)
C25D "Capacitor" 0603C 86.5,95.5 r90 bottom value="3,3 н" (schematic designator C25)
C26A "Capacitor" 0603C 127,95.5 r90 bottom value="3,3 н" (schematic designator C26)
C26B "Capacitor" 0603C 114,95.5 r90 bottom value="3,3 н" (schematic designator C26)
C26C "Capacitor" 0603C 101,95.5 r90 bottom value="3,3 н" (schematic designator C26)
C26D "Capacitor" 0603C 88,95.5 r90 bottom value="3,3 н" (schematic designator C26)
C27A "Capacitor" 0603C 117.5,94 r0 bottom value="10 мк" (schematic designator C27)
C27B "Capacitor" 0603C 104.5,94 r0 bottom value="10 мк" (schematic designator C27)
C27C "Capacitor" 0603C 91.5,94 r0 bottom value="10 мк" (schematic designator C27)
C27D "Capacitor" 0603C 78.5,94 r0 bottom value="10 мк" (schematic designator C27)
C28A "Capacitor" 0603C 117.5,92.5 r0 bottom value="0,1 мк" (schematic designator C28)
C28B "Capacitor" 0603C 104.5,92.5 r0 bottom value="0,1 мк" (schematic designator C28)
C28C "Capacitor" 0603C 91.5,92.5 r0 bottom value="0,1 мк" (schematic designator C28)
C28D "Capacitor" 0603C 78.5,92.5 r0 bottom value="0,1 мк" (schematic designator C28)
C29A "Capacitor" 0603C 123.5,103.5 r90 bottom value="3,3 н" (schematic designator C29)
C29B "Capacitor" 0603C 110.5,103.5 r90 bottom value="3,3 н" (schematic designator C29)
C29C "Capacitor" 0603C 97.5,103.5 r90 bottom value="3,3 н" (schematic designator C29)
C29D "Capacitor" 0603C 84.5,103.5 r90 bottom value="3,3 н" (schematic designator C29)
C30A "Capacitor" 0603C 121.5,103.5 r90 bottom value="3,3 н" (schematic designator C30)
C30B "Capacitor" 0603C 108.5,103.5 r90 bottom value="3,3 н" (schematic designator C30)
C30C "Capacitor" 0603C 95.5,103.5 r90 bottom value="3,3 н" (schematic designator C30)
C30D "Capacitor" 0603C 82.5,103.5 r90 bottom value="3,3 н" (schematic designator C30)
C31A "Capacitor" 0603C 125.5,115 r180 bottom value="0,1 мк" (schematic designator C31)
C31B "Capacitor" 0603C 112.5,115 r180 bottom value="0,1 мк" (schematic designator C31)
C31C "Capacitor" 0603C 99.5,115 r180 bottom value="0,1 мк" (schematic designator C31)
C31D "Capacitor" 0603C 86.5,115 r180 bottom value="0,1 мк" (schematic designator C31)
C32A "Capacitor" 0603C 125.5,112.5 r90 bottom value="3,3 н" (schematic designator C32)
C32B "Capacitor" 0603C 112.5,112.5 r90 bottom value="3,3 н" (schematic designator C32)
C32C "Capacitor" 0603C 99.5,112.5 r90 bottom value="3,3 н" (schematic designator C32)
C32D "Capacitor" 0603C 86.5,112.5 r90 bottom value="3,3 н" (schematic designator C32)
C33A "Capacitor" 0603C 127,112.5 r90 bottom value="3,3 н" (schematic designator C33)
C33B "Capacitor" 0603C 114,112.5 r90 bottom value="3,3 н" (schematic designator C33)
C33C "Capacitor" 0603C 101,112.5 r90 bottom value="3,3 н" (schematic designator C33)
C33D "Capacitor" 0603C 88,112.5 r90 bottom value="3,3 н" (schematic designator C33)
C34 "Capacitor" 1206C 106,118.5 r180 top value="4,7 мк"
C35 "Capacitor" 0603C 102.75,93 r0 top value="0,47 мк"
C36 "Capacitor" 0603C 105,102 r90 top value="0,1 мк"
C37 "Capacitor" 0603C 90,95.75 r90 top value="0,1 мк"
C38 "Capacitor" 0603C 85,102 r270 top value="0,1 мк"
C39 "Capacitor" 0603C 88.5,117.5 r180 top value="0,1 мк"
C40 "Capacitor" 0603C 105.75,96.5 r180 top value="1 мк"
C41 "Capacitor" 0603C 99,95.75 r90 top value="1 мк"
C42 "Capacitor" 0603C 104.5,114.5 r90 top value="0,1 мк"
C43 "Capacitor" 0603C 105.75,98 r180 top value="0,1 мк"
C44 "Capacitor" 0603C 100.5,95.75 r90 top value="0,1 мк"
C45 "Capacitor" 1206C 88.5,119.5 r0 top value="2,2 мк"
C46 "Capacitor" 1206C 107.5,114 r270 top value="2,2 мк"
C47 "Capacitor" 0603C 97.25,95.75 r90 top value="12 п"
C48 "Capacitor" 0603C 91.5,95.75 r270 top value="12 п"
C49 "Capacitor" 0603C 82.2,96.2 r180 top value="0,1 мк"
C50 "Capacitor" 0603C 86.5,96.5 r180 top value="0,1 мк"
C51 "Capacitor" 1210C 86,136 r90 top value="10 мк"
C52 "Capacitor" 0603C 102.5,123 r90 bottom value="0,1 мк"
C53 "Capacitor" 0603C 90,133 r180 top value="0,1 мк"
C54 "Capacitor" 0603C 92,135.5 r270 top value="3,3 н"
C55 "Capacitor" 1210C 100,129.5 r270 top value="22 мк"
C56 "Capacitor" 1210C 108.1,131.8 r180 top value="10 мк"
C57 "Capacitor" 1210C 97,129.5 r270 top value="22 мк"
C58 "Capacitor" 1210C 94,129.5 r270 top value="22 мк"
C59 "Capacitor" 0603C 104,131.5 r270 top value="1 мк"
C60 "Capacitor" 1210C 86,142 r90 bottom value="10 мк"
C61 "Capacitor" 0603C 93.5,142.5 r90 bottom value="0,1 мк"
C62 "Capacitor" 0603C 91,140.5 r0 bottom value="3,3 н"
C63 "Capacitor" 0603C 96.5,123 r90 bottom value="1 мк"
C64 "Capacitor" 1210C 107.5,142.5 r270 bottom value="22 мк"
C65 "Capacitor" 1210C 104.5,142.5 r270 bottom value="22 мк"
C66 "Capacitor" 1210C 101.5,142.5 r270 bottom value="22 мк"
C67 "Capacitor" 0603C 90.5,135 r0 bottom value="0,1 мк"
D1 "LD1117S33CTR" SOT223 106.5,125.5 r270 top
DA1A "AD8031" SOT23-5 117.5,103 r90 bottom (schematic designator DA1)
DA1B "AD8031" SOT23-5 104.5,103 r90 bottom (schematic designator DA1)
DA1C "AD8031" SOT23-5 91.5,103 r90 bottom (schematic designator DA1)
DA1D "AD8031" SOT23-5 78.5,103 r90 bottom (schematic designator DA1)
DA2 "REF3030AIDBZR" SOT23-3 102.75,95.5 r270 top
DA3 "AP63200" TSOT26 89.5,135.5 r180 top
DA4 "AP63200" TSOT26 91,143 r90 bottom
DA5 "ADP150AUJZ-3.3" SOT23-5 99.5,123 r180 bottom
DD1 "UCC27211" SOIC-8 115.5,135 r180 bottom
DD2 "UCC27211" SOIC-8 126,143 r180 bottom
DD3A "AD8656" SOIC-8 122,94 r90 bottom (schematic designator DD3)
DD3B "AD8656" SOIC-8 109,94 r90 bottom (schematic designator DD3)
DD3C "AD8656" SOIC-8 96,94 r90 bottom (schematic designator DD3)
DD3D "AD8656" SOIC-8 83,94 r90 bottom (schematic designator DD3)
DD4A "AD8656" SOIC-8 122,111 r90 bottom (schematic designator DD4)
DD4B "AD8656" SOIC-8 109,111 r90 bottom (schematic designator DD4)
DD4C "AD8656" SOIC-8 96,111 r90 bottom (schematic designator DD4)
DD4D "AD8656" SOIC-8 83,111 r90 bottom (schematic designator DD4)
DD5 "STM32H743VIT6" LQFP100 95,108 r90 top
DD6 "MAX485CSA" SOIC-8 91,132 r180 bottom
DD7 "MAX3051EKA+T" SOT23-8 91,126 r180 bottom
FB1 "BLM18AG102SN1D" 0603L 105.75,99.5 r180 top
HL1 "LED" 0805D 81,106.5 r180 top value=Зеленый
HL2 "LED" 0805D 81,104.5 r180 top value=Красный
HL3 "LED" 0805D 82.5,115 r270 top value=Желтый
HL4 "LED" 0805D 116.5,131.25 r90 top value=Желтый
L1 "Inductance_RM8" RM8_trans 139,106.5 r270 top
L2 "SP43-150K" SP43 89.5,129.5 r270 top value="15 мк"
L3 "SP43-150K" SP43 97,142.5 r0 bottom value="15 мк"
R1 "Resistor" 0603R 111,135 r270 bottom value="10 к"
R2 "Resistor" 0603R 121.5,143 r270 bottom value="10 к"
R3 "Resistor" 0603R 111,132.5 r90 bottom value="10 к"
R4 "Resistor" 0603R 121.5,140.35 r90 bottom value="10 к"
R5 "Resistor" 0603R 120.5,134.5 r0 bottom value=3,3
R6 "Resistor" 0603R 120.5,133 r0 bottom value=3,3
R7 "Resistor" 0603R 131,142.5 r0 bottom value=3,3
R8 "Resistor" 0603R 131,141 r0 bottom value=3,3
R9 "Resistor" 0805R 127,126.9 r90 top value=47
R10 "Resistor" 0805R 141.1,142.2 r180 top value=47
R11 "Resistor" 2512R 135.5,92.5 r0 top value=33
R12 "Resistor" 2512R 135.5,88.5 r0 top value=33
R13 "Resistor" 2512R 143.5,92.5 r0 top value=33
R14 "Resistor" 2512R 143.5,88.5 r0 top value=33
R15A "Resistor" 0805R 121,83.5 r90 bottom value="1 к" (schematic designator R15)
R15B "Resistor" 0805R 108,83.5 r90 bottom value="1 к" (schematic designator R15)
R15C "Resistor" 0805R 95,83.5 r90 bottom value="1 к" (schematic designator R15)
R15D "Resistor" 0805R 82,83.5 r90 bottom value="1 к" (schematic designator R15)
R16A "Resistor" 0603R 123.5,88 r180 bottom value="1,0 к" (schematic designator R16)
R16B "Resistor" 0603R 110.5,88 r180 bottom value="1,0 к" (schematic designator R16)
R16C "Resistor" 0603R 97.5,88 r180 bottom value="1,0 к" (schematic designator R16)
R16D "Resistor" 0603R 84.5,88 r180 bottom value="1,0 к" (schematic designator R16)
R17A "Resistor" 0603R 120.5,89.5 r0 bottom value="470 к" (schematic designator R17)
R17B "Resistor" 0603R 107.5,89.5 r0 bottom value="470 к" (schematic designator R17)
R17C "Resistor" 0603R 94.5,89.5 r0 bottom value="470 к" (schematic designator R17)
R17D "Resistor" 0603R 81.5,89.5 r0 bottom value="470 к" (schematic designator R17)
R18A "Resistor" 0603R 117.5,95.5 r0 bottom value="12 к" (schematic designator R18)
R18B "Resistor" 0603R 104.5,95.5 r0 bottom value="12 к" (schematic designator R18)
R18C "Resistor" 0603R 91.5,95.5 r0 bottom value="12 к" (schematic designator R18)
R18D "Resistor" 0603R 78.5,95.5 r0 bottom value="12 к" (schematic designator R18)
R19A "Resistor" 0603R 117.5,97 r180 bottom value="10 к" (schematic designator R19)
R19B "Resistor" 0603R 104.5,97 r180 bottom value="10 к" (schematic designator R19)
R19C "Resistor" 0603R 91.5,97 r180 bottom value="10 к" (schematic designator R19)
R19D "Resistor" 0603R 78.5,97 r180 bottom value="10 к" (schematic designator R19)
R20A "Resistor" 0603R 123.5,89.5 r0 bottom value="10 к" (schematic designator R20)
R20B "Resistor" 0603R 110.5,89.5 r0 bottom value="10 к" (schematic designator R20)
R20C "Resistor" 0603R 97.5,89.5 r0 bottom value="10 к" (schematic designator R20)
R20D "Resistor" 0603R 84.5,89.5 r0 bottom value="10 к" (schematic designator R20)
R21A "Resistor" 0603R 127,92.5 r270 bottom value="8,2 к" (schematic designator R21)
R21B "Resistor" 0603R 114,92.5 r270 bottom value="8,2 к" (schematic designator R21)
R21C "Resistor" 0603R 101,92.5 r270 bottom value="8,2 к" (schematic designator R21)
R21D "Resistor" 0603R 88,92.5 r270 bottom value="8,2 к" (schematic designator R21)
R22A "Resistor" 0603R 125.5,92.5 r90 bottom value=620 (schematic designator R22)
R22B "Resistor" 0603R 112.5,92.5 r90 bottom value=620 (schematic designator R22)
R22C "Resistor" 0603R 99.5,92.5 r90 bottom value=620 (schematic designator R22)
R22D "Resistor" 0603R 86.5,92.5 r90 bottom value=620 (schematic designator R22)
R23A "Resistor" 0603R 117.5,106 r0 bottom value="4,7 к" (schematic designator R23)
R23B "Resistor" 0603R 104.5,106 r0 bottom value="4,7 к" (schematic designator R23)
R23C "Resistor" 0603R 91.5,106 r0 bottom value="4,7 к" (schematic designator R23)
R23D "Resistor" 0603R 78.5,106 r0 bottom value="4,7 к" (schematic designator R23)
R24A "Resistor" 0603R 122,98.5 r180 bottom value="4,7 к" (schematic designator R24)
R24B "Resistor" 0603R 109,98.5 r180 bottom value="4,7 к" (schematic designator R24)
R24C "Resistor" 0603R 96,98.5 r180 bottom value="4,7 к" (schematic designator R24)
R24D "Resistor" 0603R 83,98.5 r180 bottom value="4,7 к" (schematic designator R24)
R25A "Resistor" 0603R 123.5,100.5 r90 bottom value=560 (schematic designator R25)
R25B "Resistor" 0603R 110.5,100.5 r90 bottom value=560 (schematic designator R25)
R25C "Resistor" 0603R 97.5,100.5 r90 bottom value=560 (schematic designator R25)
R25D "Resistor" 0603R 84.5,100.5 r90 bottom value=560 (schematic designator R25)
R26A "Resistor" 0603R 121.5,100.5 r90 bottom value=220 (schematic designator R26)
R26B "Resistor" 0603R 108.5,100.5 r90 bottom value=220 (schematic designator R26)
R26C "Resistor" 0603R 95.5,100.5 r90 bottom value=220 (schematic designator R26)
R26D "Resistor" 0603R 82.5,100.5 r90 bottom value=220 (schematic designator R26)
R27A "Resistor" 0603R 123,106 r0 bottom value="6,2 к" (schematic designator R27)
R27B "Resistor" 0603R 110,106 r0 bottom value="6,2 к" (schematic designator R27)
R27C "Resistor" 0603R 97,106 r0 bottom value="6,2 к" (schematic designator R27)
R27D "Resistor" 0603R 84,106 r0 bottom value="6,2 к" (schematic designator R27)
R28A "Resistor" 0603R 127,109.5 r90 bottom value=560 (schematic designator R28)
R28B "Resistor" 0603R 114,109.5 r90 bottom value=560 (schematic designator R28)
R28C "Resistor" 0603R 101,109.5 r90 bottom value=560 (schematic designator R28)
R28D "Resistor" 0603R 88,109.5 r90 bottom value=560 (schematic designator R28)
R29A "Resistor" 0603R 125.5,109.5 r90 bottom value="1,5 к" (schematic designator R29)
R29B "Resistor" 0603R 112.5,109.5 r90 bottom value="1,5 к" (schematic designator R29)
R29C "Resistor" 0603R 99.5,109.5 r90 bottom value="1,5 к" (schematic designator R29)
R29D "Resistor" 0603R 86.5,109.5 r90 bottom value="1,5 к" (schematic designator R29)
R30A "Resistor" 0603R 122,115.5 r0 bottom value="16 к" (schematic designator R30)
R30B "Resistor" 0603R 109,115.5 r0 bottom value="16 к" (schematic designator R30)
R30C "Resistor" 0603R 96,115.5 r0 bottom value="16 к" (schematic designator R30)
R30D "Resistor" 0603R 83,115.5 r0 bottom value="16 к" (schematic designator R30)
R31A "Resistor" 0603R 122.5,117.5 r90 bottom value=220 (schematic designator R31)
R31B "Resistor" 0603R 109.5,117.5 r90 bottom value=220 (schematic designator R31)
R31C "Resistor" 0603R 96.5,117.5 r90 bottom value=220 (schematic designator R31)
R31D "Resistor" 0603R 83.5,117.5 r90 bottom value=220 (schematic designator R31)
R32 "Resistor" 0603R 84.75,104.5 r0 top value="10 к"
R33 "Resistor" 0603R 97.5,119.2 r90 top value=200
R34 "Resistor" 0603R 96,119.2 r90 top value=200
R35 "Resistor" 0603R 94.5,119.2 r90 top value=200
R36 "Resistor" 0603R 93,119.2 r90 top value=200
R37 "Resistor" 0603R 105.9,107.6 r0 top value=200
R38 "Resistor" 0603R 105.9,104.6 r0 top value=200
R39 "Resistor" 0603R 105.9,109.1 r0 top value=200
R40 "Resistor" 0603R 105.9,106.1 r0 top value=200
R41 "Resistor" 0603R 82.2,97.7 r0 top value="10 к"
R42 "Resistor" 0603R 100.5,119.2 r90 top value=0
R43 "Resistor" 0603R 99,119.2 r90 top value=0
R44 "Resistor" 0603R 78,107 r270 top value="1,0 к"
R45 "Resistor" 0603R 78,103.85 r90 top value="1,0 к"
R46 "Resistor" 0603R 86.5,98 r0 top value="10 к"
R47 "Resistor" 0603R 92.5,138 r180 top value="1,0 к"
R48 "Resistor" 0603R 93.5,135.5 r270 top value="5,1 к"
R49 "Resistor" 0603R 104,123 r90 bottom value="10 к"
R50 "Resistor" 0603R 88.5,140.5 r90 bottom value="1,0 к"
R51 "Resistor" 0603R 91,139 r180 bottom value="11 к"
R52 "Resistor" 0603R 84.25,115 r270 top value="1,0 к"
R53 "Resistor" 0603R 114.5,131.25 r90 top value="10 к"
R54 "Resistor" 0603R 85,126.5 r90 bottom value="10 к"
R55 "Resistor" 1206R 86,132 r90 bottom value=120
R56 "Resistor" 0603R 87.5,146.625 r0 top value="100 к"
R57 "Resistor" 0603R 91,128.5 r180 bottom value=3,3
S1 "TSS-TD-19XA-XTR" TSS-TD-19XA-XTR 80,90.5 r270 top
S2 "TSS-TD-19XA-XTR" TSS-TD-19XA-XTR 85.5,90.5 r270 top
T1 "Transformer_RM8" RM8_trans 139,129.5 r0 top
VD1 "SMA4007" SMA 138.5,82 r90 top
VD2 "SMA4007" SMA 142,82 r270 top
VD3A "BAV99" SOT23-3 123.5,85.5 r180 bottom (schematic designator VD3)
VD3B "BAV99" SOT23-3 110.5,85.5 r180 bottom (schematic designator VD3)
VD3C "BAV99" SOT23-3 97.5,85.5 r180 bottom (schematic designator VD3)
VD3D "BAV99" SOT23-3 84.5,85.5 r180 bottom (schematic designator VD3)
VD4 "PSM712" SOT23-3 82.5,132 r180 bottom
VD5 "USBLC6-4" SOT23-6 82,122.5 r270 bottom
VD6 "BZV55-B12" mini_MELF_3.5mm 94,146 r180 top value="12 В"
VD7 "USBLC6-4" SOT23-6 115,119.5 r270 top
VT1 "CSD18534Q5A" SON-8_5x6 122.5,132.5 r90 top
VT2 "CSD18534Q5A" SON-8_5x6 122.5,140 r90 top
VT3 "CSD18534Q5A" SON-8_5x6 135.463,146.5 r180 top
VT4 "CSD18534Q5A" SON-8_5x6 128.5,146.5 r180 top
VT5 "AO3401A" SOT23-3 81.964,126.525 r180 bottom
VT6 "IRF9310TR" SOIC-8 87.5,143.125 r180 top
XP1 "XT30UPB-M" XT30UPB-M 79,138 r270 top
XP2 "CWF-2" CWF-2 78.525,127.5 r90 top
XP3 "PLS-6" PLS6 78,122.7 r0 top
XP4 "CWF-2" CWF-2 114,125 r0 top
XP5 "CWF-2" CWF-2 134,78.525 r180 top
XP6 "CWF-2" CWF-2 113.5,78.525 r180 top
XP7 "CWF-2" CWF-2 100.5,78.525 r180 top
XP8 "CWF-2" CWF-2 87.5,78.5 r180 top
ZQ1 "X322525MOB4SI" X322525MOB4SI 94.5,95.75 r180 top value="25 МГц"

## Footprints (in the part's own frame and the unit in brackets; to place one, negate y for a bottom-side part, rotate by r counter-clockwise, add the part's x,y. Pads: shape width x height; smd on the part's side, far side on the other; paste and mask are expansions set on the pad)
0603C [mm] "Chip Resistor, 2-Leads, Body 1,40x0,80mm, IPC Medium Density"
  rect 0.9x1.05 smd: 1(-0.8,0) 2(0.8,0)
  silkscreen extent -0.5,-0.77 0.5,0.77, body extent -0.85,-0.45 0.85,0.45, height 0.9
0603L [mm] "Chip Inductor, 2-Leads, Body 1,55x0,85mm, IPC Medium Density"
  rect 0.9x1.05 smd: 1(-0.8,0) 2(0.8,0)
  silkscreen extent -0.5,-0.77 0.5,0.77, body extent -0.8,-0.45 0.8,0.45, height 0.45
0603R [mm] "Chip Resistor, 2-Leads, Body 1.60x0.85mm, IPC Medium Density"
  rect 0.8x0.95 smd: 1(-0.725,0) 2(0.725,0)
  silkscreen extent -0.5,-0.72 0.5,0.72, body extent -0.8,-0.4 0.8,0.4, height 0.45
0805D [mm]
  rect 1.4x1.5 smd: 1(-1,0) 2(1,0)
  silkscreen extent -0.6,-1.07 1.97,1.07, body extent -1.07,-0.7 1.07,0.7, height 0.7
0805R [mm]
  rect 1.4x1.5 smd: 1(-1,0) 2(1,0)
  silkscreen extent -0.6,-1.07 0.6,1.07, body extent -1,-0.63 1,0.63, height 0.6
1206C [mm]
  rect 1.4x2 smd paste+0: 1(-1.8,0) 2(1.8,0)
  silkscreen extent -0.77,-0.92 0.77,0.92, body extent -1.6,-0.74 1.6,0.86, height 1.59
1206R [mm]
  rect 1.05x1.72 smd: 1(-1.46,0) 2(1.46,0)
  silkscreen extent -0.63,-0.8 0.63,0.8, body extent -1.55,-0.77 1.55,0.77, height 0.65
1210C [mm]
  rect 0.954x2.706 smd paste+0: 1(-1.625,0) 2(1.625,0)
  silkscreen extent -0.75,-1.28 0.75,1.28, body extent -1.6,-1.25 1.6,1.25, height 2.7
2512R [mm]
  rrect7% 1.9x3.37 smd: 1(-2.66,0) 2(2.66,0)
  silkscreen extent -1.25,-1.6 1.25,1.6, body extent -3.17,-1.6 3.17,1.6, height 0.65
CAP_SMD_10x12,7 [mm]
  rect 4.4x1.9 smd: 1(-4.35,0) 2(4.35,0)
  silkscreen extent -6.2,-5.15 5.15,5.15, body extent -5.5,-5.15 5.5,5.15, height 12.6
CWF-2 [mm]
  rect 1.6x1.6 hole 1 paste-2539.97 mask+0: 1(2.5,0.025)
  round 1.6 hole 1 paste-2539.97 mask+0: 2(0,0.025)
  silkscreen extent -2.51,-3.37 5.62,2.22, body extent -2.5,-3.52 5,2.23, height 7
LQFP100 [mm] "TSQFP, 100-Leads, Body 14,00x14,00mm, Pitch 0,50mm, IPC Medium Density"
  oval 1.45x0.3 smd: 1(-7.725,6) 2(-7.725,5.5) 3(-7.725,5) 4(-7.725,4.5) 5(-7.725,4) 6(-7.725,3.5) 7(-7.725,3) 8(-7.725,2.5) 9(-7.725,2) 10(-7.725,1.5) 11(-7.725,1) 12(-7.725,0.5) 13(-7.725,0) 14(-7.725,-0.5) 15(-7.725,-1) 16(-7.725,-1.5) 17(-7.725,-2) 18(-7.725,-2.5) 19(-7.725,-3) 20(-7.725,-3.5) 21(-7.725,-4) 22(-7.725,-4.5) 23(-7.725,-5) 24(-7.725,-5.5) 25(-7.725,-6) 51(7.725,-6) 52(7.725,-5.5) 53(7.725,-5) 54(7.725,-4.5) 55(7.725,-4) 56(7.725,-3.5) 57(7.725,-3) 58(7.725,-2.5) 59(7.725,-2) 60(7.725,-1.5) 61(7.725,-1) 62(7.725,-0.5) 63(7.725,0) 64(7.725,0.5) 65(7.725,1) 66(7.725,1.5) 67(7.725,2) 68(7.725,2.5) 69(7.725,3) 70(7.725,3.5) 71(7.725,4) 72(7.725,4.5) 73(7.725,5) 74(7.725,5.5) 75(7.725,6)
  oval 0.3x1.45 smd: 26(-6,-7.725) 27(-5.5,-7.725) 28(-5,-7.725) 29(-4.5,-7.725) 30(-4,-7.725) 31(-3.5,-7.725) 32(-3,-7.725) 33(-2.5,-7.725) 34(-2,-7.725) 35(-1.5,-7.725) 36(-1,-7.725) 37(-0.5,-7.725) 38(0,-7.725) 39(0.5,-7.725) 40(1,-7.725) 41(1.5,-7.725) 42(2,-7.725) 43(2.5,-7.725) 44(3,-7.725) 45(3.5,-7.725) 46(4,-7.725) 47(4.5,-7.725) 48(5,-7.725) 49(5.5,-7.725) 50(6,-7.725) 76(6,7.725) 77(5.5,7.725) 78(5,7.725) 79(4.5,7.725) 80(4,7.725) 81(3.5,7.725) 82(3,7.725) 83(2.5,7.725) 84(2,7.725) 85(1.5,7.725) 86(1,7.725) 87(0.5,7.725) 88(0,7.725) 89(-0.5,7.725) 90(-1,7.725) 91(-1.5,7.725) 92(-2,7.725) 93(-2.5,7.725) 94(-3,7.725) 95(-3.5,7.725) 96(-4,7.725) 97(-4.5,7.725) 98(-5,7.725) 99(-5.5,7.725) 100(-6,7.725)
  silkscreen extent -7.85,-6.6 6.6,6.82, body extent -8,-8 8,8, height 1.6
mini_MELF_3.5mm [mm]
  rect 1.11x1.73 smd: 1(1.705,0) 2(-1.705,0)
  silkscreen extent -3.1,-0.75 0.83,0.75, body extent -1.75,-0.8 1.75,0.8, height 1.6
PLS6 [mm]
  round 2 hole 1: 1(0,0) 2(0,-2.54) 3(0,-5.08) 4(0,-7.62) 5(0,-10.16) 6(0,-12.7)
  silkscreen extent -1.25,-14.1 1.25,1.4, body extent -1.27,-13.97 1.27,1.27, height 8.44
RM8_trans [mm]
  round 1.8 hole 1: 1(-6.35,3.81) 2(-8.89,3.81) 3(-8.89,6.35) 4(-6.35,8.89) 5(-3.81,8.89) 6(-3.81,6.35) 7(6.35,-3.81) 8(8.89,-3.81) 9(8.89,-6.35) 10(6.35,-8.89) 11(3.81,-8.89) 12(3.81,-6.35)
  round 2 hole 1.3: G1(-8.89,-8.89) G2(8.89,8.89)
  silkscreen extent -10.16,-10.16 10.16,10.16, body extent -10.16,-10.16 10.16,10.16, height 16.5
SMA [mm]
  rect 2.12x1.5 smd: 1(2.115,0) 2(-2.115,0)
  silkscreen extent -3.1,-1.35 2.16,1.28, body extent -2.57,-1.28 2.57,1.28, height 2.5
SOIC-8 [mm] "for operational amplifier"
  rect 1.45x0.6 smd: 1(-2.725,1.905) 2(-2.725,0.635) 3(-2.725,-0.635) 4(-2.725,-1.905) 5(2.725,-1.905) 6(2.725,-0.635) 7(2.725,0.635) 8(2.725,1.905)
  silkscreen extent -2.85,-2.5 1.6,2.88, body extent -3,-2.5 3,2.5, height 1.75
SON-8_5x6 [mm]
  rect 0.75x0.675 smd paste-1: 1(-2.612,1.913) 2(-2.612,0.638) 3(-2.612,-0.637) 4(-2.612,-1.912)
  rect 4.3x4.5 smd paste-2539.97: 5(0.463,0)
  rect 1.3x0.675 smd paste-1: 5(2.613,-1.912) 5(2.613,-0.637) 5(2.613,0.638) 5(2.613,1.913)
  silkscreen extent -3.71,-2.57 3.02,2.58, body extent -2.86,-2.45 3.14,2.45, height 1.1
SOT23-3 [mil]
  rect 30x30 smd: 1(-44.29,37.4) 2(-44.29,-37.6) 3(45.71,-0.1)
  silkscreen extent -25,-59 26,59, body extent -48,-60 50,59, height 41
SOT23-5 [mm]
  rect 1.32x0.59 smd: 1(-1.145,0.95) 2(-1.145,0) 3(-1.145,-0.95) 4(1.145,-0.95) 5(1.145,0.95)
  silkscreen extent -1.37,-1.4 0.25,1.75, body extent -1.4,-1.45 1.4,1.45, height 1.45
SOT23-6 [mm]
  rect 0.6x1.2 smd: 1(-0.95,-1.15) 2(0,-1.15) 3(0.95,-1.15) 4(0.95,1.15) 5(0,1.15) 6(-0.95,1.15)
  silkscreen extent -1.65,-1.65 1.6,0.5, body extent -1.46,-1.4 1.46,1.4, height 1.4
SOT23-8 [mm]
  rrect50% 1.21x0.48 smd paste+0 mask+0.102: 1(-1.255,0.975) 2(-1.255,0.325) 3(-1.255,-0.325) 4(-1.255,-0.975) 5(1.255,-0.975) 6(1.255,-0.325) 7(1.255,0.325) 8(1.255,0.975)
  silkscreen extent -2.5,-1.54 0.88,1.54, body extent -1.4,-1.45 1.4,1.45, height 1.45
SOT223 [mm] "SOT223, ld1117"
  rect 2.15x0.9 smd: 1(-2.925,2.3) 2(-2.925,0) 3(-2.925,-2.3)
  rect 2.15x3.25 smd: 2(2.925,0)
  silkscreen extent -3.05,-3.35 1.55,3.43, body extent -3.56,-3.3 3.51,3.2, height 1.6
SP43 [mm]
  rect 2x4.5 smd: 1(-1.5,0) 2(1.5,0)
  silkscreen extent -1.2,-2.5 1.3,2.5, body extent -2,-2.22 2,2.22, height 3.19
TSOT26 [mm]
  rect 0.645x0.9 smd: 1(-0.95,-1.15) 2(0,-1.15) 3(0.95,-1.15) 4(0.95,1.15) 5(0,1.15) 6(-0.95,1.15)
  silkscreen extent -1.58,-1.95 1.57,0.5, body extent -1.5,-1.4 1.5,1.4, height 1.01
TSS-TD-19XA-XTR [mm]
  rect 1.1x1 smd: 1(-3.65,0) 2(3.65,0)
  silkscreen extent -3.1,-1.9 3.1,1.9, body extent -4.05,-1.85 4.05,1.85, height 2.55
X322525MOB4SI [mm]
  rect 1.4x1.2 smd: 1(-1.1,-0.85) 2(1.1,-0.85) 3(1.1,0.85) 4(-1.1,0.85)
  silkscreen extent -2.2,-0.65 -2.1,-0.55, body extent -1.68,-1.33 1.68,1.33, height 0.9
XT30UPB-M [mm]
  round 2.7 hole 1.8: N(2.5,0)
  rect 2.7x2.7 hole 1.8: P(-2.5,0)
  silkscreen extent -5.1,-2.6 5.1,2.6, body extent -5.1,-2.6 5.1,2.6, height 10.7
